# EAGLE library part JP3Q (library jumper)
JUMPER
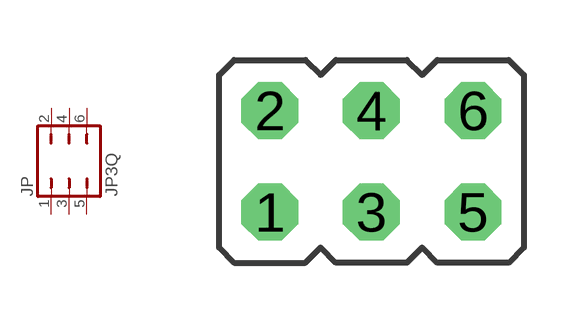
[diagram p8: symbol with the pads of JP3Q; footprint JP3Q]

Designator prefix JP

## JP3Q  [JP3Q]
1  1  pas
2  2  pas
3  3  pas
4  4  pas
5  5  pas
6  6  pas

## Footprint JP3Q (pad centres in mm)
JUMPER
drill 0.914 octagon: 1 -2.54,-1.27; 2 -2.54,1.27; 3 0,-1.27; 4 0,1.27; 5 2.54,-1.27; 6 2.54,1.27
